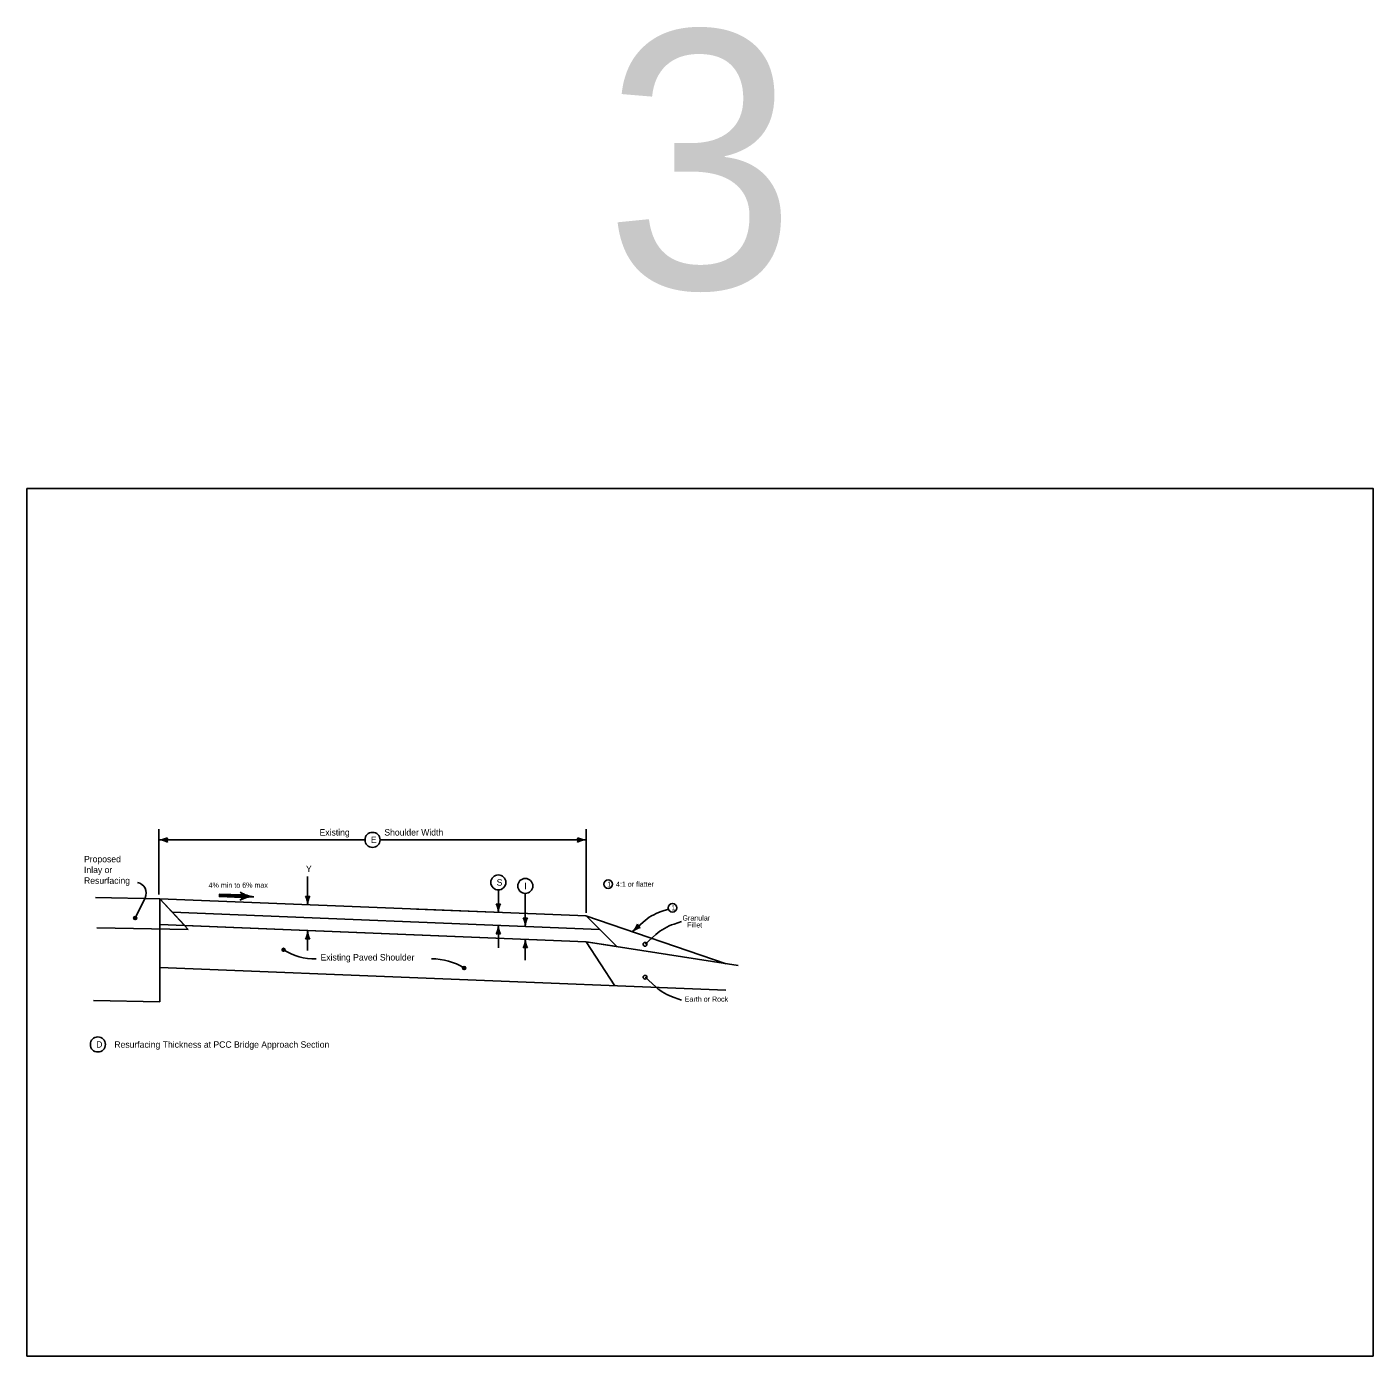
# Model space of a CAD drawing. Extents: x 10133 to 81668, y 7924 to 12229.
# Drawn here: x 17333 to 20468, y 7924 to 11018 of the extents above; entities that cross this region are included whole.
import ezdxf

# ---------------------------------------------------------------- set-up
doc = ezdxf.new("R2010")
doc.units = 0
for name, color, linetype in [('Default', 7, 'Continuous'), ('Level 11', 7, 'Continuous'), ('Level 2', 7, 'Continuous'), ('Level 20', 7, 'Continuous'), ('Level 4', 7, 'Continuous'), ('SheetBorder', 7, 'Continuous'), ('SheetText', 7, 'Continuous')]:
    doc.layers.add(name, color=color, linetype=linetype)

msp = doc.modelspace()

# ---------------------------------------------------------------- linework, layer by layer
at = {"layer": 'Default'}
for p, q in [((17700, 8926), (17642.4, 8988.3)), ((17642.4, 8988.3), (18634.9, 8948.6)), ((18634.9, 8948.6), (18706.1, 8877.3)), ((18634.7, 8888.6), (17700, 8926)), ((18706.1, 8877.3), (18634.7, 8888.6))]:
    msp.add_line(p, q, dxfattribs=at)
at = {"layer": 'Level 11'}
for p, q in [((17640, 9150.7), (17640, 8998.4)), ((17640, 9125.7), (17659.3, 9125.7)), ((17640, 9125.7), (18119.9, 9125.7)), ((18154.9, 9125.7), (18634.7, 9125.7)), ((18634.7, 9125.7), (18615.4, 9125.7)), ((18634.7, 9150.7), (18634.7, 8955.5)), ((17986.2, 9040.7), (17986.2, 8974.6)), ((17833.9, 8997.6), (17833.9, 8997.6)), ((18430.4, 8956.8), (18430.4, 9009.1)), ((18493.2, 8924.2), (18493.2, 9000.9)), ((17492.5, 8991.3), (17642.4, 8988.3)), ((17607.9, 8991.1), (17584.6, 8943.7)), ((17642.4, 8988.3), (18634.7, 8948.6)), ((17642.4, 8988.3), (17642.4, 8928.3)), ((17642.4, 8988.3), (17708.3, 8917)), ((17834, 8994.4), (17781, 8996.5)), ((17833.7, 8991.4), (17833.7, 8991.4)), ((17986.2, 8974.6), (17986.2, 8993.8)), ((18430.4, 8956.8), (18430.4, 8976)), ((17671.2, 8957.1), (18666.1, 8917.3)), ((18240, 8964.4), (18440, 8956.4)), ((18493.2, 8924.2), (18493.2, 8943.5)), ((18634.5, 8948.9), (18960.6, 8837.3)), ((18634.6, 8948.9), (18706.1, 8877.3)), ((18826.3, 8964.4), (18809.3, 8958.7)), ((17495.2, 8921.2), (17708.3, 8917)), ((17642.4, 8928.3), (18634.7, 8888.6)), ((17642.4, 8928.3), (17642.4, 8748.3)), ((17986.2, 8914.5), (17986.2, 8868.4)), ((17986.2, 8914.5), (17986.2, 8895.3)), ((18430.4, 8874.4), (18430.4, 8926.8)), ((18430.4, 8926.8), (18430.4, 8907.5)), ((18767.6, 8934.4), (18742.7, 8912.1)), ((18742.7, 8912.1), (18757.1, 8924.9)), ((18493.2, 8894.3), (18493.2, 8875)), ((18493.2, 8845.4), (18493.2, 8894.2)), ((18634.7, 8888.6), (18989, 8832.9)), ((18634.7, 8888.6), (18701.4, 8785.8)), ((17642.4, 8828.2), (18959.8, 8775.5)), ((17487.7, 8751.4), (17642.4, 8748.3))]:
    msp.add_line(p, q, dxfattribs=at)
for points in [[(17658.9, 9122.1), (17658.1, 9125.7), (17658.9, 9129.3), (17654.6, 9127.2), (17647.8, 9125.7), (17655.1, 9124), (17658.3, 9122.5), (17657.5, 9125.7), (17657.8, 9128), (17655, 9126.6), (17651.2, 9125.7), (17655.2, 9124.5), (17657.3, 9123.8), (17656.9, 9126.8), (17654.1, 9125.7), (17656.3, 9125), (17656.3, 9126), (17655.3, 9125.7)], [(18615.8, 9129.2), (18616.6, 9125.6), (18615.8, 9122), (18620.1, 9124.1), (18626.9, 9125.6), (18619.6, 9127.4), (18616.4, 9128.8), (18617.2, 9125.6), (18616.9, 9123.3), (18619.7, 9124.7), (18623.5, 9125.6), (18619.5, 9126.8), (18617.4, 9127.5), (18617.8, 9124.5), (18620.6, 9125.6), (18618.4, 9126.3), (18618.4, 9125.3), (18619.4, 9125.6)], [(17834, 8997.4), (17781.1, 8999.5), (17780.8, 8993.5), (17833.7, 8991.4), (17833.8, 8996.5), (17781.7, 8998.8), (17781.7, 8994), (17832.6, 8992.2), (17832.9, 8995.8), (17782.4, 8998), (17782.4, 8994.8), (17832, 8992.8), (17832.2, 8995.1), (17783, 8997.3), (17783, 8995.5), (17831.3, 8993.6)], [(17832.7, 9001.3), (17834.8, 8997.7), (17834.9, 8992.4), (17832.8, 8987.9), (17840.7, 8990.9), (17850, 8993.2), (17852.6, 8993.7), (17846, 8995.2), (17836.5, 8998.9), (17833.7, 9000.6), (17834.4, 8989.4), (17848.7, 8993.6), (17835, 8998.3), (17835.3, 8990.6), (17845.1, 8993.8), (17836.3, 8996.4), (17835.7, 8991.9), (17842, 8993.7), (17837.3, 8995.2), (17837, 8993.1), (17839.2, 8993.7)], [(17989.7, 8993.4), (17986.2, 8992.7), (17982.6, 8993.4), (17984.6, 8989.1), (17986.2, 8982.3), (17987.9, 8989.6), (17989.3, 8992.8), (17986.2, 8992), (17983.8, 8992.3), (17985.2, 8989.5), (17986.2, 8985.7), (17987.3, 8989.7), (17988.1, 8991.8), (17985, 8991.4), (17986.2, 8988.6), (17986.9, 8990.8), (17985.8, 8990.9), (17986.1, 8989.8)], [(18433.9, 8975.6), (18430.4, 8974.9), (18426.7, 8975.6), (18428.8, 8971.3), (18430.4, 8964.5), (18432.1, 8971.9), (18433.5, 8975), (18430.4, 8974.2), (18428, 8974.5), (18429.4, 8971.7), (18430.4, 8967.9), (18431.5, 8971.9), (18432.2, 8974.1), (18429.2, 8973.7), (18430.4, 8970.9), (18431, 8973.1), (18430, 8973.1), (18430.3, 8972.1)], [(17584.3, 8940.5), (17585.5, 8941), (17587.3, 8941.6), (17587.7, 8943.5), (17587.4, 8945.1), (17586.3, 8946.6), (17584.5, 8946.5), (17582.7, 8946.2), (17581.8, 8944.7), (17581.6, 8943.2), (17582.7, 8941.2), (17584.1, 8941), (17585.9, 8941.5), (17587.4, 8942.6), (17587.4, 8944.4), (17586.2, 8945.8), (17584.5, 8946), (17582.7, 8945.6), (17582.4, 8944.6), (17582, 8943.3), (17582.9, 8941.8), (17584.2, 8941.8), (17585.8, 8942.1), (17586.9, 8942.9), (17586.3, 8944.5), (17585.2, 8945.4), (17583.6, 8945.4), (17583.2, 8944.6), (17582.8, 8943.6), (17583.5, 8942.4), (17584.6, 8942.2), (17585.7, 8942.7), (17585.7, 8943.8), (17585.2, 8944.6), (17584.2, 8944.9), (17583.7, 8944.5), (17583.4, 8943.9), (17583.9, 8943), (17584.6, 8942.8), (17585.3, 8943.2), (17585.2, 8943.8), (17584.7, 8944.2), (17584, 8944.2), (17584, 8943.7), (17584.6, 8943.4)], [(18496.7, 8943.1), (18493.2, 8942.3), (18489.6, 8943.1), (18491.6, 8938.8), (18493.2, 8932), (18494.9, 8939.3), (18496.3, 8942.5), (18493.2, 8941.7), (18490.9, 8942), (18492.2, 8939.2), (18493.2, 8935.4), (18494.3, 8939.4), (18495.1, 8941.5), (18492, 8941.1), (18493.2, 8938.3), (18493.9, 8940.5), (18492.8, 8940.5), (18493.1, 8939.5)], [(17982.6, 8895.7), (17986.2, 8896.4), (17989.8, 8895.7), (17987.7, 8900), (17986.2, 8906.8), (17984.5, 8899.4), (17983.1, 8896.3), (17986.2, 8897.1), (17988.5, 8896.8), (17987.2, 8899.6), (17986.2, 8903.4), (17985, 8899.4), (17984.3, 8897.3), (17987.4, 8897.6), (17986.2, 8900.4), (17985.5, 8898.2), (17986.6, 8898.2), (17986.2, 8899.2)], [(18426.8, 8907.9), (18430.4, 8908.7), (18434, 8907.9), (18431.9, 8912.2), (18430.4, 8919), (18428.7, 8911.7), (18427.3, 8908.5), (18430.4, 8909.3), (18432.7, 8909), (18431.3, 8911.8), (18430.4, 8915.6), (18429.2, 8911.6), (18428.5, 8909.5), (18431.6, 8909.9), (18430.4, 8912.7), (18429.7, 8910.5), (18430.7, 8910.5), (18430.4, 8911.5)], [(18759.1, 8922), (18756.2, 8924.2), (18754.4, 8927.4), (18752.6, 8923), (18748.5, 8917.3), (18755.1, 8920.9), (18758.4, 8922), (18755.7, 8923.8), (18754.4, 8925.7), (18753.2, 8922.8), (18751, 8919.6), (18754.8, 8921.4), (18756.9, 8922.2), (18754.5, 8924.3), (18753.2, 8921.5), (18755.3, 8922.5), (18754.6, 8923.3), (18754.1, 8922.3)], [(17930.4, 8873), (17929.3, 8872.5), (17927.4, 8871.9), (17927.1, 8870.1), (17927.3, 8868.4), (17928.5, 8866.9), (17930.2, 8867.1), (17932.1, 8867.3), (17933, 8868.8), (17933.1, 8870.4), (17932, 8872.4), (17930.7, 8872.6), (17928.9, 8872.1), (17927.3, 8870.9), (17927.4, 8869.2), (17928.6, 8867.8), (17930.2, 8867.6), (17932.1, 8868), (17932.3, 8869), (17932.7, 8870.2), (17931.8, 8871.8), (17930.5, 8871.7), (17929, 8871.5), (17927.9, 8870.6), (17928.4, 8869.1), (17929.6, 8868.2), (17931.1, 8868.1), (17931.5, 8869), (17932, 8869.9), (17931.2, 8871.1), (17930.1, 8871.4), (17929.1, 8870.9), (17929, 8869.7), (17929.6, 8868.9), (17930.6, 8868.6), (17931.1, 8869.1), (17931.4, 8869.7), (17930.9, 8870.6), (17930.1, 8870.8), (17929.4, 8870.4), (17929.5, 8869.7), (17930.1, 8869.3), (17930.8, 8869.4), (17930.8, 8869.9), (17930.1, 8870.2)], [(18489.6, 8875.4), (18493.2, 8876.1), (18496.8, 8875.4), (18494.7, 8879.7), (18493.2, 8886.5), (18491.5, 8879.2), (18490.1, 8876), (18493.2, 8876.8), (18495.5, 8876.5), (18494.2, 8879.3), (18493.2, 8883.1), (18492, 8879.1), (18491.3, 8877), (18494.4, 8877.4), (18493.2, 8880.2), (18492.5, 8878), (18493.6, 8878), (18493.2, 8879)], [(18350.5, 8824.1), (18351.7, 8824.7), (18353.5, 8825.2), (18353.9, 8827.1), (18353.6, 8828.7), (18352.4, 8830.2), (18350.7, 8830.1), (18348.8, 8829.8), (18348, 8828.4), (18347.8, 8826.8), (18348.9, 8824.8), (18350.2, 8824.6), (18352.1, 8825.1), (18353.6, 8826.3), (18353.5, 8828), (18352.4, 8829.4), (18350.7, 8829.6), (18348.9, 8829.2), (18348.6, 8828.2), (18348.2, 8826.9), (18349.1, 8825.4), (18350.4, 8825.5), (18352, 8825.7), (18353.1, 8826.6), (18352.5, 8828.1), (18351.3, 8829), (18349.8, 8829), (18349.4, 8828.2), (18348.9, 8827.3), (18349.7, 8826.1), (18350.8, 8825.8), (18351.8, 8826.3), (18351.9, 8827.5), (18351.4, 8828.3), (18350.3, 8828.5), (18349.8, 8828.1), (18349.5, 8827.5), (18350.1, 8826.6), (18350.8, 8826.4), (18351.5, 8826.8), (18351.4, 8827.4), (18350.9, 8827.8), (18350.1, 8827.8), (18350.2, 8827.3), (18350.8, 8827)]]:
    msp.add_lwpolyline(points, dxfattribs=at)
for centre, radius in [((18137.4, 9125.7), 17.5), ((18430.4, 9026.6), 17.5), ((18493.2, 9018.4), 17.5), ((18686.3, 9022.5), 10), ((18835.8, 8967.6), 10), ((17584.6, 8943.7), 3.5), ((17930.2, 8869.8), 3.5), ((18350.8, 8827.3), 3.5), ((17497.7, 8649.4), 17.5)]:
    msp.add_circle(centre, radius, dxfattribs=at)
for centre, radius, start, end in [((17640, 9168.2), 42.5, 270, 298.0725), ((17640, 9083.2), 42.5, 61.9275, 90), ((17675.7, 9125.7), 16.4, 162.2666, 197.7334), ((18599, 9125.7), 16.4, 342.2666, 17.7333), ((18634.7, 9168.2), 42.5, 241.9275, 270), ((18634.7, 9083.2), 42.5, 90, 118.0725), ((17585.4, 9002.1), 25, 333.8677, 79.2889), ((17823, 8994.8), 11.3, 299.4247, 55.9953), ((17865.4, 9057.6), 64.5, 235.9957, 266.0257), ((17860.2, 8928.8), 64.5, 89.3942, 119.4242), ((17986.2, 9010.2), 16.4, 252.2666, 287.7333), ((17943.7, 8974.6), 42.5, 0, 28.0725), ((18028.7, 8974.6), 42.5, 151.9275, 180), ((18430.4, 8992.4), 16.4, 252.2666, 287.7333), ((18387.9, 8956.8), 42.5, 0, 28.0725), ((18472.9, 8956.8), 42.5, 151.9275, 180), ((18493.2, 8959.9), 16.4, 252.2666, 287.7333), ((18450.7, 8924.2), 42.5, 0, 28.0725), ((18535.7, 8924.2), 42.5, 151.9275, 180), ((18847.6, 8844.9), 120, 108.6256, 131.8315), ((17943.7, 8914.5), 42.5, 331.9275, 0), ((18028.7, 8914.5), 42.5, 180, 208.0725), ((18387.9, 8926.8), 42.5, 331.9275, 0), ((18430.4, 8891.1), 16.4, 72.2666, 107.7334), ((18472.9, 8926.8), 42.5, 180, 208.0725), ((18714.4, 8943.8), 42.5, 311.8315, 339.904), ((18771.1, 8880.5), 42.5, 103.759, 131.8315), ((18769.3, 8935.9), 16.4, 204.0981, 239.5648), ((17986.2, 8878.9), 16.4, 72.2666, 107.7334), ((18450.7, 8894.3), 42.5, 331.9275, 0), ((18493.2, 8858.6), 16.4, 72.2666, 107.7334), ((18535.7, 8894.3), 42.5, 180, 208.0725), ((18002.7, 8982.7), 134.2, 237.2893, 271.3894), ((18278.2, 8714.4), 134.2, 57.2893, 91.3894)]:
    msp.add_arc(centre, radius, start, end, dxfattribs=at)
at = {"layer": 'Level 20'}
msp.add_line((18217.6, 8849.4), (18217.6, 8849.4), dxfattribs=at)
at = {"layer": 'Level 4'}
for p, q in [((18856.8, 8935.7), (18839.5, 8929.8)), ((18797.2, 8905.2), (18772, 8882.6)), ((18797.2, 8783.3), (18772, 8805.9)), ((18856.8, 8752.8), (18839.5, 8758.6))]:
    msp.add_line(p, q, dxfattribs=at)
for centre in [(18772, 8882.6), (18772, 8805.9)]:
    msp.add_circle(centre, 4.4, dxfattribs=at)
for centre, start, end in [((18878.5, 8814.3), 108.6256, 131.8315), ((18878.5, 8874.1), 228.1685, 251.3744)]:
    msp.add_arc(centre, 121.9, start, end, dxfattribs=at)
at = {"layer": 'SheetBorder'}
msp.add_lwpolyline([(17332.5, 9944), (20467.5, 9944), (20467.5, 7924), (17332.5, 7924)], close=True, dxfattribs=at)

# ---------------------------------------------------------------- texts
at = {"layer": 'Level 2'}
for s, height, p in [('Existing ', 15, (18014, 9135.7)), ('E', 15, (18133.4, 9118.2)), ('Shoulder Width', 15, (18164.9, 9135.7)), ('Proposed', 15, (17465.5, 9073.4)), ('Inlay or', 15, (17465.5, 9048.4)), ('Y', 15, (17982.3, 9050.7)), ('Resurfacing', 15, (17465.5, 9023.4)), ('S', 15, (18426.5, 9019.1)), ('4:1 or flatter', 12, (18704.3, 9016.5)), ('4% min to 6% max', 12, (17755.6, 9014.3)), ('I', 15, (18490.7, 9010.9)), ('1', 12, (18683.9, 9016.5)), ('1', 12, (18833.4, 8961.6)), ('Granular', 12, (18859.2, 8937.9)), ('Fillet', 12, (18870.2, 8921.7)), ('Existing Paved Shoulder', 15, (18016.3, 8844.8)), ('Earth or Rock', 12, (18864.4, 8749)), ('D', 15, (17493.8, 8641.9)), ('Resurfacing Thickness at PCC Bridge Approach Section', 15, (17536.1, 8641.7))]:
    msp.add_text(s, height=height, dxfattribs=at).set_placement(p)
at = {"layer": 'SheetText'}
msp.add_text('3', height=600, dxfattribs=at).set_placement((18677.6, 10409.2))

doc.saveas('drawing.dxf')
